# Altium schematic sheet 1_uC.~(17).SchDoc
size 414 x 293 mm; SheetNumber: 1; SheetTotal: 4
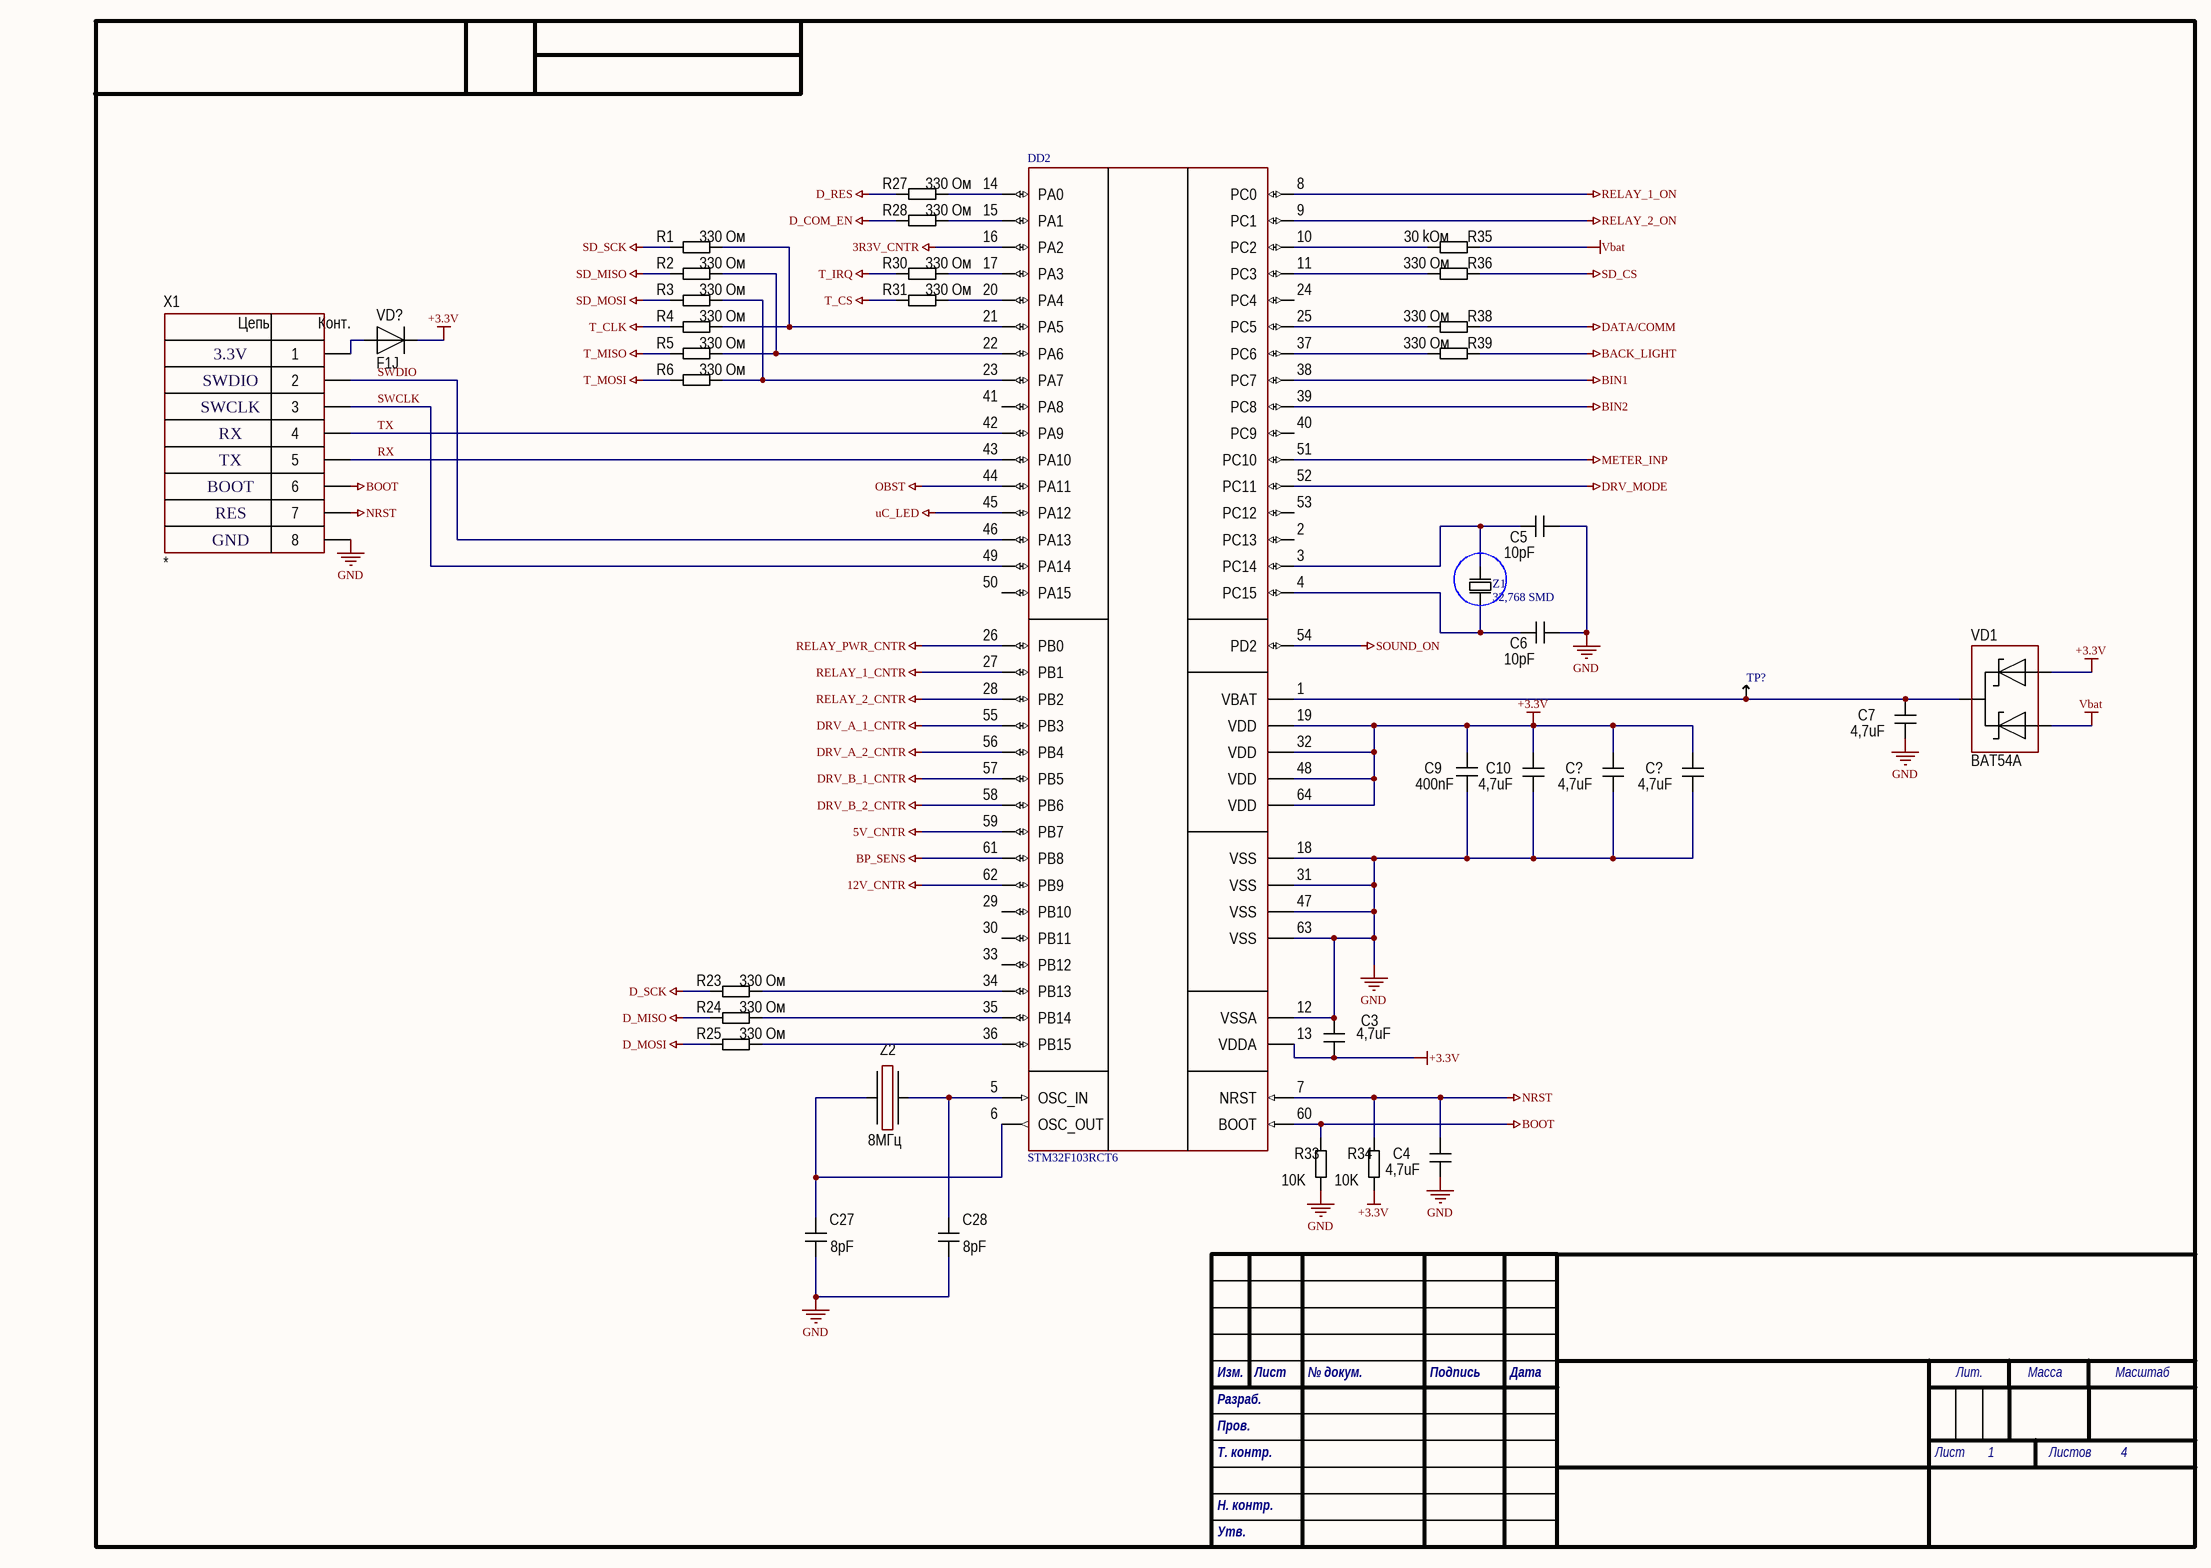
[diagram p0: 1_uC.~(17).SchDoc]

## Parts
(Parts that share a designator on the sheet are numbered #1, #2 ... from top to bottom, then left to right.)
C3  4,7uF  [CH0402C]
C4  4,7uF  [CH0402C]
C5  10pF  [CH0402C]
C6  10pF  [CH0402C]
C7  4,7uF  [CH0402C]
C9  400nF  [CH0402C]
C10  4,7uF  [CH0402C]
C27  8pF  [CH0402C]
C28  8pF  [CH0402C]
C?#1  4,7uF  [CH0402C]
C?#2  4,7uF  [CH0402C]
DD2  STM32F103RCT6  [64-LQFP]
R1  330 Ом  [CH0603R]
R2  330 Ом  [CH0603R]
R3  330 Ом  [CH0603R]
R4  330 Ом  [CH0603R]
R5  330 Ом  [CH0603R]
R6  330 Ом  [CH0603R]
R23  330 Ом  [CH0603R]
R24  330 Ом  [CH0603R]
R25  330 Ом  [CH0603R]
R27  330 Ом  [CH0603R]
R28  330 Ом  [CH0603R]
R30  330 Ом  [CH0603R]
R31  330 Ом  [CH0603R]
R33  10K  [CH0805R]
R34  10K  [CH0805R]
R35  30 kОм  [CH0603R]
R36  330 Ом  [CH0603R]
R38  330 Ом  [CH0603R]
R39  330 Ом  [CH0603R]
TP?  TestPoint  (value not drawn)
VD1  BAT54A  [SOT23_123]
VD?  F1J  [SOD123F]
X1  *  [CON: PLS-8]
Z1  32,768 SMD  [SMD 32.768KHz]
Z2  8МГц  [OSC: ABM3]

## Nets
3R3V_CNTR: DD2.16(PA2)
5V_CNTR: DD2.59(PB7)
12V_CNTR: DD2.62(PB9)
+3.3V: C3.1 C9.1 C10.2 C?#1.2 C?#2.2 DD2.13(VDDA) DD2.19(VDD) DD2.32(VDD) DD2.48(VDD) DD2.64(VDD) R34.1 VD1.1 VD?.2
BACK_LIGHT: R39.1
BIN1: DD2.38(PC7)
BIN2: DD2.39(PC8)
BOOT: DD2.60(BOOT) R33.2 X1.6
BP_SENS: DD2.61(PB8)
D_COM_EN: R28.1
D_MISO: R24.1
D_MOSI: R25.1
D_RES: R27.1
D_SCK: R23.1
DATA/COMM: R38.1
DRV_A_1_CNTR: DD2.55(PB3)
DRV_A_2_CNTR: DD2.56(PB4)
DRV_B_1_CNTR: DD2.57(PB5)
DRV_B_2_CNTR: DD2.58(PB6)
DRV_MODE: DD2.52(PC11)
GND: C3.2 C4.1 C5.2 C6.1 C7.1 C9.2 C10.1 C27.1 C28.1 C?#1.1 C?#2.1 DD2.12(VSSA) DD2.18(VSS) DD2.31(VSS) DD2.47(VSS) DD2.63(VSS) R33.1 X1.8
METER_INP: DD2.51(PC10)
NRST: C4.2 DD2.7(NRST) R34.2 X1.7
OBST: DD2.44(PA11)
RELAY_1_CNTR: DD2.27(PB1)
RELAY_1_ON: DD2.8(PC0)
RELAY_2_CNTR: DD2.28(PB2)
RELAY_2_ON: DD2.9(PC1)
RELAY_PWR_CNTR: DD2.26(PB0)
SD_CS: R36.1
SD_MISO: R2.1
SD_MOSI: R3.1
SD_SCK: R1.1
SOUND_ON: DD2.54(PD2)
T_CLK: R4.1
T_CS: R31.1
T_IRQ: R30.1
T_MISO: R5.1
T_MOSI: R6.1
uC_LED: DD2.45(PA12)
Vbat: R35.1 VD1.3
RX: DD2.43(PA10) X1.5
SWCLK: DD2.49(PA14) X1.3
SWDIO: DD2.46(PA13) X1.2
TX: DD2.42(PA9) X1.4
NetC5_1: C5.1 DD2.3(PC14) Z1.1
NetC6_2: C6.2 DD2.4(PC15) Z1.2
NetC7_2: C7.2 DD2.1(VBAT) TP?.0 VD1.2
NetC27_2: C27.2 DD2.6(OSC_OUT) Z2.1
NetC28_2: C28.2 DD2.5(OSC_IN) Z2.3
NetDD2_10: DD2.10(PC2) R35.2
NetDD2_11: DD2.11(PC3) R36.2
NetDD2_14: DD2.14(PA0) R27.2
NetDD2_15: DD2.15(PA1) R28.2
NetDD2_17: DD2.17(PA3) R30.2
NetDD2_20: DD2.20(PA4) R31.2
NetDD2_21: DD2.21(PA5) R1.2 R4.2
NetDD2_22: DD2.22(PA6) R2.2 R5.2
NetDD2_23: DD2.23(PA7) R3.2 R6.2
NetDD2_25: DD2.25(PC5) R38.2
NetDD2_34: DD2.34(PB13) R23.2
NetDD2_35: DD2.35(PB14) R24.2
NetDD2_36: DD2.36(PB15) R25.2
NetDD2_37: DD2.37(PC6) R39.2
NetVD?_1: VD?.1 X1.1

Not connected (* = marked no-connect by the designer): DD2 2(PC13) 24(PC4) 29(PB10) 30(PB11) 33(PB12) 40(PC9) 41(PA8) 50(PA15) 53(PC12)

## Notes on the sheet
- 3.3V
- SWDIO
- SWCLK
- RX
- TX
- BOOT
- RES
- GND

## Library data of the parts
C3-C6 C9 C10 C27 C28 C?#1 C?#2 = Capacitor: 0402
C7 = Capacitor
DD2 = STM32F103RCT6: Cortex-M3 (64-LQFP)
R1-R6 R23-R25 R27 R28 R30 R31 R35 R36 R38 R39 = Resistor: 0603
R33 R34 = Resistor: 0805
VD1 = Diod Schottky Array v.1: SOT-23
VD? = Diod
X1 = 8-Connector: Pin header 8
Z1 = Kvarc_32,768: 32,768 kHz SMD 8mm x 3.8mm 12,5pF
Z2 = Oscillator: NX5032GA-8MHz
